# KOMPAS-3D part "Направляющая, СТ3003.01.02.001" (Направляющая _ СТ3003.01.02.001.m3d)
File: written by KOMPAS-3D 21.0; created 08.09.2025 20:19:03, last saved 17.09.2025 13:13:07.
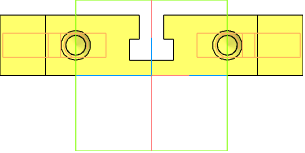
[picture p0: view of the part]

Document properties: Полное имя файла: C:\Users\1\Yandex.Disk\Документы\Новая папка\Стапель №2\Стапель _ СТ3003.00.00.000\Опора _ СТ3003.01.00.000\3D\Кронштейн _ СТ3003.01.02.000\Направляющая _ СТ3003.01.02.001.m3d

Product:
- Part/product: Направляющая  | designation СТ3003.01.02.001
    Материал: Сталь 45  ГОСТ 1050-2013 (density 7810 kg/m3)
    Масса: 1.56864
    Форматы листов документа: A3

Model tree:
1. Эскиз:1
2. Элемент выдавливания:1
     Расстояние 1 = 160
3. Эскиз:2  (with: Элемент выдавливания:1)
4. Элемент выдавливания:2
     Расстояние 2 = 20
5. Эскиз:3  (with: Элемент выдавливания:1)
6. Элемент выдавливания:3
     Расстояние 2 = 20
7. Эскиз:4  (with: Элемент выдавливания:1, Элемент выдавливания:3)
8. Элемент выдавливания:4
     Расстояние 2 = 10
9. Эскиз:6  (with: Элемент выдавливания:1)
10. ЛСК:2  (with: Плоскость XY, Плоскость ZX, Плоскость ZY, Ось X, Ось Y, Ось Z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)
     Ось X. Y = -1; Ось Y. X = 1; Ось Z. Z = 1; Координата X = 25; Координата Y = -80; Координата Z = 10; Точка начала. Х = 25; Точка начала. Y = -80; Точка начала. Z = 10
11. Эскиз:7
12. Элемент вращения:1
     Угол 1 = 360
13. Смещенная плоскость:1  (with: Элемент выдавливания:1)
     Расстояние = 0.923418
14. Условное изображение резьбы:1  (with: Элемент вращения:1)  (labels: 8x1,25)
     Длина резьбы = 19.0766; Шаг резьбы = 1.25; Номинальный диаметр резьбы = 8
15. Подгонка:1
16. Отверстие М8x20/1,6x45°
17. Эскиз:9  (with: Элемент выдавливания:1)
18. ЛСК:4  (with: Плоскость XY, Плоскость ZX, Плоскость ZY, Ось X, Ось Y, Ось Z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)
     Ось X. Y = -1; Ось Y. X = 1; Ось Z. Z = 1; Координата X = -25; Координата Y = -80; Координата Z = 10; Точка начала. Х = -25; Точка начала. Y = -80; Точка начала. Z = 10
19. Эскиз:10
20. Элемент вращения:2
     Угол 1 = 360
21. Смещенная плоскость:2  (with: Элемент выдавливания:1)
     Расстояние = 0.923418
22. Условное изображение резьбы:2  (with: Элемент вращения:2)  (labels: 8x1,25)
     Длина резьбы = 19.0766; Шаг резьбы = 1.25; Номинальный диаметр резьбы = 8
23. Подгонка:2
24. Отверстие М8x20/1,6x45° (1)
25. Эскиз:28  (with: Элемент выдавливания:2)
26. ЛСК:18  (with: Плоскость XY, Плоскость ZX, Плоскость ZY, Ось X, Ось Y, Ось Z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)
     Ось X. X = 1; Ось Y. Y = 1; Ось Z. Z = 1; Координата X = 35; Координата Y = -45; Координата Z = 10; Точка начала. Х = 35; Точка начала. Y = -45; Точка начала. Z = 10
27. Эскиз:29
28. Элемент вращения:7
     Угол 1 = 360
29. Смещенная плоскость:7  (with: Элемент выдавливания:2)
     Расстояние = 0.923418
30. Условное изображение резьбы:7  (with: Элемент вращения:7, Подгонка:1)  (labels: 8x1,25)
     Длина резьбы = 19.0766; Шаг резьбы = 1.25; Номинальный диаметр резьбы = 8
31. Отверстие М8x20/1,6x45° (2)
32. Эскиз:32  (with: Элемент выдавливания:2)
33. ЛСК:21  (with: Плоскость XY, Плоскость ZX, Плоскость ZY, Ось X, Ось Y, Ось Z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)
     Ось X. X = -1; Ось Y. Y = 1; Ось Z. Z = -1; Координата X = -35; Координата Y = -45; Координата Z = 10; Точка начала. Х = -35; Точка начала. Y = -45; Точка начала. Z = 10
34. Эскиз:33
35. Элемент вращения:8
     Угол 1 = 360
36. Смещенная плоскость:8  (with: Элемент выдавливания:2)
     Расстояние = 0.923418
37. Условное изображение резьбы:8  (with: Элемент вращения:8, Подгонка:2)  (labels: 8x1,25)
     Длина резьбы = 19.0766; Шаг резьбы = 1.25; Номинальный диаметр резьбы = 8
38. Отверстие М8x20/1,6x45° (3)
39. Эскиз:20  (with: Элемент выдавливания:1)
40. ЛСК:12  (with: Плоскость XY, Плоскость ZX, Плоскость ZY, Ось X, Ось Y, Ось Z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)
     Ось X. X = -1; Ось Y. Y = 1; Ось Z. Z = -1; Координата X = -50; Координата Y = -13; Координата Z = 10; Точка начала. Х = -50; Точка начала. Y = -13; Точка начала. Z = 10
41. Эскиз:21
42. Элемент вращения:5
     Угол 1 = 360
43. Смещенная плоскость:5  (with: Элемент выдавливания:1)
     Расстояние = 0.923418
44. Условное изображение резьбы:5  (with: Элемент вращения:5)  (labels: 8x1,25)
     Длина резьбы = 19.0766; Шаг резьбы = 1.25; Номинальный диаметр резьбы = 8
45. Подгонка:5
46. Отверстие М8x20/1,6x45° (4)
47. Эскиз:24  (with: Элемент выдавливания:1)
48. ЛСК:15  (with: Плоскость XY, Плоскость ZX, Плоскость ZY, Ось X, Ось Y, Ось Z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)
     Ось X. X = 1; Ось Y. Y = 1; Ось Z. Z = 1; Координата X = 50; Координата Y = -13; Координата Z = 10; Точка начала. Х = 50; Точка начала. Y = -13; Точка начала. Z = 10
49. Эскиз:25
50. Элемент вращения:6
     Угол 1 = 360
51. Смещенная плоскость:6  (with: Элемент выдавливания:1)
     Расстояние = 0.923418
52. Условное изображение резьбы:6  (with: Элемент вращения:6)  (labels: 8x1,25)
     Длина резьбы = 19.0766; Шаг резьбы = 1.25; Номинальный диаметр резьбы = 8
53. Подгонка:6
54. Отверстие М8x20/1,6x45° (5)  (labels: Сталь 45  ГОСТ 1050-2013)

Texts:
  KTE.LIST=LTWD36N5dmSErgwNQxupvb
  Edge1
  Edge2
  СТ3003.01.02.001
